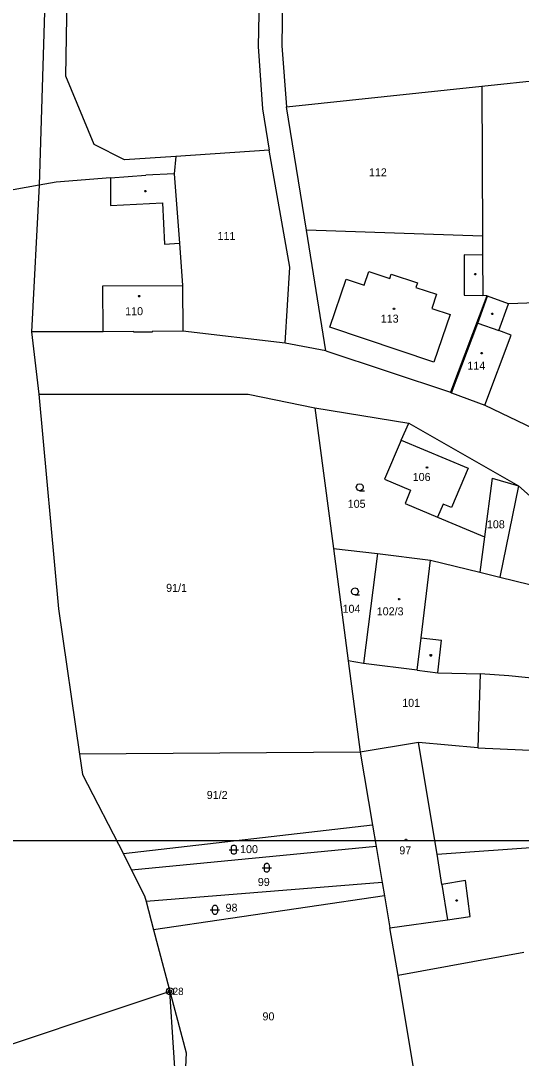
# Model space of a CAD drawing. Extents: x -812394 to -807601, y -1013097 to -1009266.
# Drawn here: x -809883 to -809776.7, y -1010813 to -1010592.7 of the extents above; entities that cross this region are included whole.
import ezdxf

# ---------------------------------------------------------------- set-up
doc = ezdxf.new("R2010")
doc.units = 0
for name, color, linetype in [('body', 7, 'Continuous'), ('cisla', 7, 'Continuous'), ('Default', 7, 'Continuous'), ('KN_HRANICE', 7, 'Continuous'), ('KN_KULTURY', 7, 'Continuous'), ('KN_PARCELY', 7, 'Continuous'), ('KN_SLUCKY', 7, 'Continuous'), ('LEGENDA', 7, 'Continuous'), ('obvod_stavby', 7, 'Continuous')]:
    doc.layers.add(name, color=color, linetype=linetype)

# ---------------------------------------------------------------- blocks, each defined once
blk = doc.blocks.new('304')
at = {"layer": 'Default'}
blk.add_lwpolyline([(0, 0), (-0.38, 0.1), (-0.65, 0.37), (-0.75, 0.74), (-0.65, 1.11), (-0.38, 1.38), (-0.01, 1.48), (0.36, 1.38), (0.63, 1.11), (0.73, 0.73), (0.63, 0.35), (0.36, 0.08), (-0.02, -0.02), (0.98, -0.02)], dxfattribs=at)
blk = doc.blocks.new('316')
at = {"layer": 'Default'}
for points in [[(-1, 1), (0.27, 1), (1, 1)], [(-0.5, 1.5), (-0.4, 1.79), (-0.15, 1.97), (0.16, 1.97), (0.41, 1.79), (0.51, 1.5), (0.51, 0.5), (0.41, 0.21), (0.16, 0.03), (-0.15, 0.03), (-0.4, 0.21), (-0.5, 0.5), (-0.5, 1.5)]]:
    blk.add_lwpolyline(points, dxfattribs=at)
blk = doc.blocks.new('402')
at = {"layer": 'Default'}
blk.add_lwpolyline([(0.09, 0.15), (0.18, 0), (0.09, -0.15), (-0.09, -0.15), (-0.18, 0), (-0.09, 0.15), (0.09, 0.15)], dxfattribs=at)

msp = doc.modelspace()

# ---------------------------------------------------------------- linework, layer by layer
at = {"layer": 'body'}
msp.add_line((-809851.28, -1010798.84), (-809851.28, -1010798.84), dxfattribs=at)
for radius in [0.75, 0.35]:
    msp.add_circle((-809851.28, -1010798.84), radius, dxfattribs=at)
at = {"layer": 'KN_HRANICE'}
for p, q in [((-809873.36, -1010604.47), (-809872.78, -1010570.15)), ((-809832.23, -1010581.05), (-809832.51, -1010598.19)), ((-809827.23, -1010580.92), (-809827.51, -1010598.06)), ((-809877.92, -1010590.8), (-809879.03, -1010627.62)), ((-809832.51, -1010598.19), (-809831.62, -1010611.42)), ((-809827.51, -1010598.06), (-809826.5, -1010610.99)), ((-809785.03, -1010606.6), (-809746.74, -1010602.54)), ((-809867.35, -1010619), (-809873.36, -1010604.47)), ((-809826.5, -1010610.99), (-809785.03, -1010606.6)), ((-809785.03, -1010606.6), (-809784.91, -1010638.49)), ((-809831.62, -1010611.42), (-809830.2, -1010620.19)), ((-809822.29, -1010637.21), (-809826.5, -1010610.99)), ((-809860.96, -1010622.27), (-809867.35, -1010619)), ((-809830.2, -1010620.19), (-809850.01, -1010621.53)), ((-809825.85, -1010645.04), (-809830.2, -1010620.19)), ((-809850.01, -1010621.53), (-809860.96, -1010622.27)), ((-809850.01, -1010621.53), (-809850.38, -1010625.24)), ((-809850.38, -1010625.24), (-809856.43, -1010625.49)), ((-809850.38, -1010625.24), (-809849.27, -1010639.96)), ((-809879.03, -1010627.62), (-809884.55, -1010628.63)), ((-809879.03, -1010627.62), (-809880.69, -1010658.8)), ((-809875.47, -1010626.99), (-809879.03, -1010627.62)), ((-809863.92, -1010626.08), (-809875.47, -1010626.99)), ((-809863.92, -1010626.08), (-809856.43, -1010625.49)), ((-809784.91, -1010638.49), (-809822.29, -1010637.21)), ((-809818.18, -1010662.82), (-809822.29, -1010637.21)), ((-809784.91, -1010638.49), (-809784.89, -1010642.49)), ((-809849.27, -1010639.96), (-809848.59, -1010648.97)), ((-809784.89, -1010642.49), (-809784.86, -1010651.09)), ((-809826.78, -1010661.18), (-809825.85, -1010645.04)), ((-809848.59, -1010648.97), (-809848.53, -1010658.67)), ((-809784.01, -1010651.14), (-809791.73, -1010671.61)), ((-809784.01, -1010651.14), (-809784.86, -1010651.09)), ((-809783.82, -1010651.21), (-809784.01, -1010651.14)), ((-809779.36, -1010652.87), (-809783.82, -1010651.21)), ((-809773.49, -1010652.65), (-809779.36, -1010652.87)), ((-809865.45, -1010658.79), (-809880.69, -1010658.8)), ((-809880.69, -1010658.8), (-809879.15, -1010672.04)), ((-809858.96, -1010658.74), (-809865.45, -1010658.79)), ((-809858.96, -1010658.89), (-809858.96, -1010658.74)), ((-809855.08, -1010658.87), (-809858.96, -1010658.89)), ((-809848.53, -1010658.67), (-809855.08, -1010658.72)), ((-809855.08, -1010658.72), (-809855.08, -1010658.87)), ((-809826.78, -1010661.18), (-809848.53, -1010658.67)), ((-809818.18, -1010662.82), (-809826.78, -1010661.18)), ((-809818.18, -1010662.82), (-809791.73, -1010671.61)), ((-809791.73, -1010671.61), (-809791.45, -1010671.71)), ((-809791.45, -1010671.71), (-809784.4, -1010674.33)), ((-809879.15, -1010672.04), (-809834.64, -1010672.02)), ((-809879.15, -1010672.04), (-809874.93, -1010717.6)), ((-809834.64, -1010672.02), (-809820.53, -1010674.93)), ((-809820.53, -1010674.93), (-809816.51, -1010704.77)), ((-809820.53, -1010674.93), (-809800.51, -1010678.2)), ((-809784.4, -1010674.33), (-809774.04, -1010679.33)), ((-809802.14, -1010681.76), (-809800.51, -1010678.2)), ((-809800.51, -1010678.2), (-809777.22, -1010691.48)), ((-809802.14, -1010681.76), (-809805.72, -1010690.09)), ((-809805.72, -1010690.09), (-809800.16, -1010692.42)), ((-809782.82, -1010689.83), (-809784.46, -1010702.29)), ((-809782.82, -1010689.83), (-809777.22, -1010691.48)), ((-809777.22, -1010691.48), (-809781.21, -1010710.87)), ((-809777.22, -1010691.48), (-809766.01, -1010701.62)), ((-809800.16, -1010692.42), (-809801.34, -1010695.22)), ((-809801.34, -1010695.22), (-809794.45, -1010698.17)), ((-809794.45, -1010698.17), (-809784.46, -1010702.29)), ((-809784.46, -1010702.29), (-809785.46, -1010709.82)), ((-809816.51, -1010704.77), (-809813.43, -1010728.67)), ((-809816.51, -1010704.77), (-809807.17, -1010705.86)), ((-809807.17, -1010705.86), (-809810.15, -1010729.19)), ((-809807.17, -1010705.86), (-809795.91, -1010707.24)), ((-809797.91, -1010723.76), (-809795.91, -1010707.24)), ((-809795.91, -1010707.24), (-809785.46, -1010709.82)), ((-809785.46, -1010709.82), (-809781.21, -1010710.87)), ((-809781.21, -1010710.87), (-809771.66, -1010713.22)), ((-809874.93, -1010717.6), (-809870.46, -1010748.48)), ((-809798.74, -1010730.64), (-809797.91, -1010723.76)), ((-809813.43, -1010728.67), (-809810.87, -1010748.08)), ((-809810.15, -1010729.19), (-809813.43, -1010728.67)), ((-809798.74, -1010730.64), (-809810.15, -1010729.19)), ((-809798.74, -1010730.64), (-809794.37, -1010731.2)), ((-809794.37, -1010731.2), (-809785.42, -1010731.43)), ((-809785.42, -1010731.43), (-809785.91, -1010747.13)), ((-809779.32, -1010731.85), (-809785.42, -1010731.43)), ((-809752.63, -1010734.46), (-809779.32, -1010731.85)), ((-809798.52, -1010745.99), (-809810.87, -1010748.08)), ((-809785.91, -1010747.13), (-809798.52, -1010745.99)), ((-809794.5, -1010769.7), (-809798.52, -1010745.99)), ((-809810.87, -1010748.08), (-809870.46, -1010748.48)), ((-809870.46, -1010748.48), (-809869.85, -1010752.77)), ((-809810.87, -1010748.08), (-809808.24, -1010763.58)), ((-809785.91, -1010747.13), (-809765.89, -1010748.07)), ((-809869.85, -1010752.77), (-809861.14, -1010769.64)), ((-809808.24, -1010763.58), (-809861.14, -1010769.64)), ((-809808.24, -1010763.58), (-809807.48, -1010768.06)), ((-809807.48, -1010768.06), (-809859.41, -1010773.1)), ((-809807.48, -1010768.06), (-809806.19, -1010775.7)), ((-809794.5, -1010769.7), (-809750.96, -1010766.66)), ((-809861.14, -1010769.64), (-809859.41, -1010773.1)), ((-809793.54, -1010776.17), (-809794.5, -1010769.7)), ((-809859.41, -1010773.1), (-809856.66, -1010778.59)), ((-809806.19, -1010775.7), (-809856.35, -1010779.75)), ((-809806.19, -1010775.7), (-809805.71, -1010778.53)), ((-809788.53, -1010775.31), (-809793.54, -1010776.17)), ((-809787.51, -1010782.96), (-809788.53, -1010775.31)), ((-809856.66, -1010778.59), (-809856.35, -1010779.75)), ((-809805.71, -1010778.53), (-809854.75, -1010785.76)), ((-809805.71, -1010778.53), (-809804.56, -1010785.33)), ((-809856.35, -1010779.75), (-809854.75, -1010785.76)), ((-809804.56, -1010785.33), (-809792.3, -1010783.63)), ((-809792.3, -1010783.63), (-809787.51, -1010782.96)), ((-809854.75, -1010785.76), (-809847.8, -1010811.91)), ((-809802.82, -1010795.47), (-809804.56, -1010785.33)), ((-809776.12, -1010790.59), (-809802.82, -1010795.47)), ((-809795, -1010842.25), (-809802.82, -1010795.47)), ((-809847.8, -1010811.91), (-809848.47, -1010824.63))]:
    msp.add_line(p, q, dxfattribs=at)
at = {"layer": 'KN_SLUCKY'}
for p, q in [((-809863.92, -1010626.08), (-809863.87, -1010631.99)), ((-809863.87, -1010631.99), (-809852.85, -1010631.39)), ((-809852.85, -1010631.39), (-809852.45, -1010640.17)), ((-809852.45, -1010640.17), (-809849.27, -1010639.96)), ((-809788.76, -1010642.46), (-809788.8, -1010650.98)), ((-809784.89, -1010642.49), (-809788.76, -1010642.46)), ((-809810.03, -1010648.9), (-809809.06, -1010645.99)), ((-809809.06, -1010645.99), (-809804.61, -1010647.48)), ((-809804.61, -1010647.48), (-809804.3, -1010646.54)), ((-809804.3, -1010646.54), (-809798.72, -1010648.4)), ((-809865.55, -1010649.04), (-809848.59, -1010648.97)), ((-809865.45, -1010658.79), (-809865.55, -1010649.04)), ((-809817.34, -1010657.79), (-809813.83, -1010647.63)), ((-809813.83, -1010647.63), (-809810.03, -1010648.9)), ((-809798.72, -1010648.4), (-809799.03, -1010649.34)), ((-809799.03, -1010649.34), (-809794.68, -1010650.8)), ((-809794.68, -1010650.8), (-809795.68, -1010653.8)), ((-809788.8, -1010650.98), (-809784.86, -1010651.09)), ((-809785.89, -1010656.93), (-809783.82, -1010651.21)), ((-809781.46, -1010658.5), (-809779.36, -1010652.87)), ((-809791.45, -1010671.71), (-809785.89, -1010656.93)), ((-809785.89, -1010656.93), (-809781.46, -1010658.5)), ((-809778.83, -1010659.48), (-809781.46, -1010658.5)), ((-809784.4, -1010674.33), (-809778.83, -1010659.48)), ((-809802.14, -1010681.76), (-809787.93, -1010687.73)), ((-809787.93, -1010687.73), (-809791.51, -1010696.11)), ((-809793.26, -1010695.37), (-809794.45, -1010698.17)), ((-809791.51, -1010696.11), (-809793.26, -1010695.37)), ((-809797.91, -1010723.76), (-809793.59, -1010724.28)), ((-809794.37, -1010731.2), (-809793.59, -1010724.28)), ((-809793.54, -1010776.17), (-809792.3, -1010783.63))]:
    msp.add_line(p, q, dxfattribs=at)
msp.add_lwpolyline([(-809795.68, -1010653.8), (-809791.74, -1010655.11), (-809795.22, -1010665.26), (-809817.34, -1010657.79)], dxfattribs=at)
at = {"layer": 'LEGENDA'}
msp.add_lwpolyline([(-810040.19, -1011186.89), (-809446.19, -1011186.89), (-809446.19, -1010766.89), (-810040.19, -1010766.89)], close=True, dxfattribs=at)
at = {"layer": 'obvod_stavby'}
msp.add_lwpolyline([(-809819.54, -1010907.68), (-809820.27, -1010877.38), (-809829.44, -1010832), (-809848.99, -1010834.52), (-809851.28, -1010798.84), (-809898.47, -1010814.6), (-809898.21, -1010828.41), (-809894.78, -1010861.65), (-809893.92, -1010865.41), (-809892.39, -1010868.68), (-809890.33, -1010872.36)], dxfattribs=at)

# ---------------------------------------------------------------- block references
at = {"layer": 'KN_KULTURY'}
for name, p in [('402', (-809856.47, -1010628.94)), ('402', (-809786.45, -1010646.52)), ('402', (-809857.81, -1010651.2)), ('402', (-809803.7, -1010653.89)), ('402', (-809782.84, -1010654.95)), ('402', (-809785.08, -1010663.3)), ('402', (-809796.68, -1010687.62)), ('304', (-809810.97, -1010692.52)), ('304', (-809811.97, -1010714.65)), ('402', (-809802.61, -1010715.55)), ('402', (-809795.87, -1010727.49)), ('316', (-809837.72, -1010769.76)), ('402', (-809801.13, -1010766.65)), ('316', (-809830.72, -1010773.59)), ('402', (-809790.39, -1010779.57)), ('316', (-809841.72, -1010782.52))]:
    msp.add_blockref(name, p, dxfattribs=at)

# ---------------------------------------------------------------- texts
at = {"layer": 'cisla'}
msp.add_text(' 28', height=1.552, dxfattribs=at).set_placement((-809851.26, -1010799.62))
at = {"layer": 'KN_PARCELY'}
for s, p in [('112', (-809809.01, -1010625.77)), ('111', (-809841.17, -1010639.28)), ('110', (-809860.78, -1010655.25)), ('113', (-809806.51, -1010656.83)), ('114', (-809788.11, -1010666.82)), ('106', (-809799.72, -1010690.45)), ('105', (-809813.52, -1010696.15)), ('108', (-809783.96, -1010700.5)), ('91/1', (-809852.08, -1010714)), ('104', (-809814.62, -1010718.45)), ('102/3', (-809807.36, -1010718.99)), ('101', (-809801.95, -1010738.42)), ('91/2', (-809843.46, -1010757.98)), ('100', (-809836.38, -1010769.49)), ('97', (-809802.56, -1010769.74)), ('99', (-809832.61, -1010776.46)), ('98', (-809839.46, -1010781.92)), ('90', (-809831.62, -1010805))]:
    msp.add_text(s, height=1.7, dxfattribs=at).set_placement(p)

doc.saveas('drawing.dxf')
